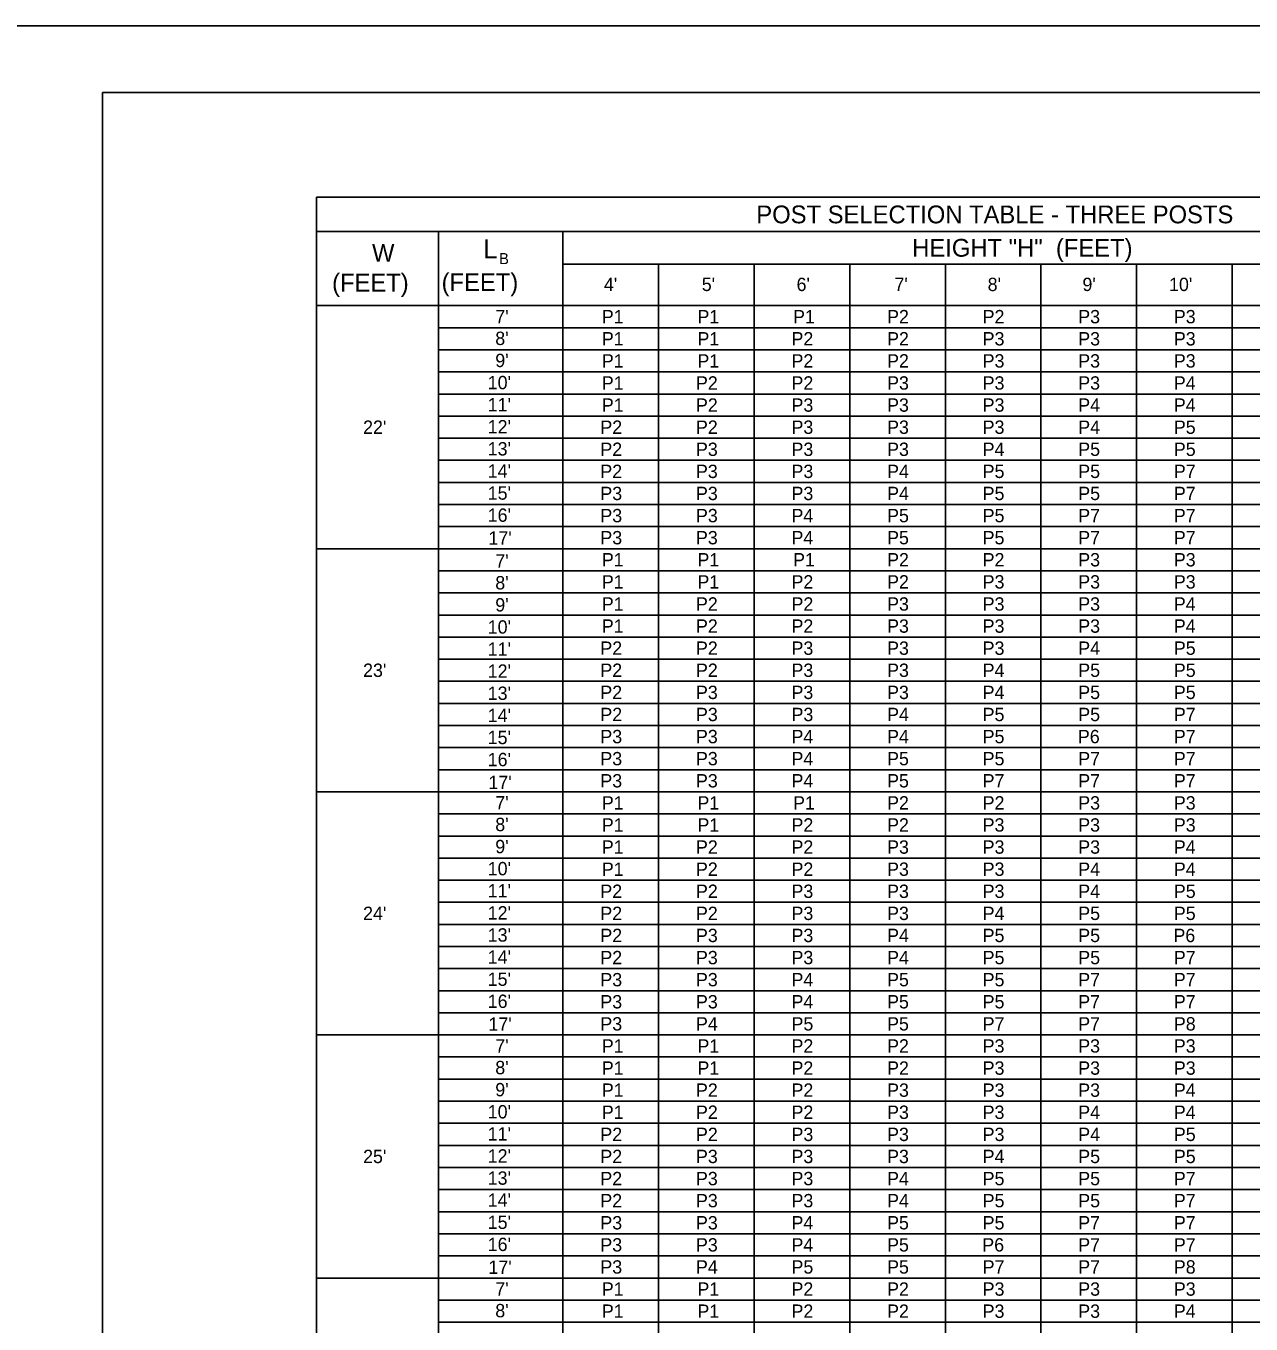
# Model space of a CAD drawing. Extents: x 637580 to 641008, y 294594 to 295782.
# Drawn here: x 640126.1 to 640401.8, y 295489.6 to 295781.6 of the extents above; entities that cross this region are included whole.
import ezdxf

# ---------------------------------------------------------------- set-up
doc = ezdxf.new("R2010")
doc.units = 0
for name, color, linetype in [('1', 7, 'Continuous'), ('2', 7, 'Continuous'), ('PLT-BNDY', 7, 'Continuous')]:
    doc.layers.add(name, color=color, linetype=linetype)

msp = doc.modelspace()

# ---------------------------------------------------------------- linework, layer by layer
at = {"layer": '1'}
for p, q in [((640143.31, 295766.63), (640929.31, 295766.63)), ((640143.31, 295766.63), (640143.31, 295202.63)), ((640191.43, 295226.43), (640191.43, 295743.08)), ((640191.43, 295743.08), (640526.66, 295743.08)), ((640191.43, 295735.41), (640526.66, 295735.41)), ((640218.95, 295226.43), (640218.95, 295735.41)), ((640191.43, 295718.7), (640526.66, 295718.7)), ((640191.43, 295664.01), (640526.66, 295664.01)), ((640191.43, 295609.31), (640526.66, 295609.31)), ((640191.43, 295554.61), (640526.66, 295554.61)), ((640191.43, 295499.91), (640526.66, 295499.91))]:
    msp.add_line(p, q, dxfattribs=at)
at = {"layer": '2'}
for p, q in [((640246.95, 295226.43), (640246.95, 295735.41)), ((640246.95, 295728.06), (640526.66, 295728.06)), ((640268.47, 295226.43), (640268.47, 295728.06)), ((640289.99, 295226.43), (640289.99, 295728.06)), ((640311.5, 295226.43), (640311.5, 295728.06)), ((640333.02, 295226.43), (640333.02, 295728.06)), ((640354.53, 295226.43), (640354.53, 295728.06)), ((640376.05, 295226.43), (640376.05, 295728.06)), ((640397.56, 295226.43), (640397.56, 295728.06)), ((640211.96, 295718.7), (640526.66, 295718.7)), ((640218.95, 295713.73), (640526.66, 295713.73)), ((640218.95, 295708.76), (640526.66, 295708.76)), ((640218.95, 295703.79), (640526.66, 295703.79)), ((640218.95, 295698.81), (640526.66, 295698.81)), ((640218.95, 295693.84), (640526.66, 295693.84)), ((640218.95, 295688.87), (640526.66, 295688.87)), ((640218.95, 295683.9), (640526.66, 295683.9)), ((640218.95, 295678.92), (640526.66, 295678.92)), ((640218.95, 295673.95), (640526.66, 295673.95)), ((640218.95, 295668.98), (640526.66, 295668.98)), ((640218.95, 295659.03), (640526.66, 295659.03)), ((640218.95, 295654.06), (640526.66, 295654.06)), ((640218.95, 295649.09), (640526.66, 295649.09)), ((640218.95, 295644.12), (640526.66, 295644.12)), ((640218.95, 295639.14), (640526.66, 295639.14)), ((640218.95, 295634.17), (640526.66, 295634.17)), ((640218.95, 295629.2), (640526.66, 295629.2)), ((640218.95, 295624.23), (640526.66, 295624.23)), ((640218.95, 295619.25), (640526.66, 295619.25)), ((640218.95, 295614.28), (640526.66, 295614.28)), ((640218.95, 295604.34), (640526.66, 295604.34)), ((640218.95, 295599.36), (640526.66, 295599.36)), ((640218.95, 295594.39), (640526.66, 295594.39)), ((640218.95, 295589.42), (640526.66, 295589.42)), ((640218.95, 295584.45), (640526.66, 295584.45)), ((640218.95, 295579.47), (640526.66, 295579.47)), ((640218.95, 295574.5), (640526.66, 295574.5)), ((640218.95, 295569.53), (640526.66, 295569.53)), ((640218.95, 295564.56), (640526.66, 295564.56)), ((640218.95, 295559.58), (640526.66, 295559.58)), ((640218.95, 295549.64), (640526.66, 295549.64)), ((640218.95, 295544.67), (640526.66, 295544.67)), ((640218.95, 295539.69), (640526.66, 295539.69)), ((640218.95, 295534.72), (640526.66, 295534.72)), ((640218.95, 295529.75), (640526.66, 295529.75)), ((640218.95, 295524.78), (640526.66, 295524.78)), ((640218.95, 295519.8), (640526.66, 295519.8)), ((640218.95, 295514.83), (640526.66, 295514.83)), ((640218.95, 295509.86), (640526.66, 295509.86)), ((640218.95, 295504.89), (640526.66, 295504.89)), ((640218.95, 295494.94), (640526.66, 295494.94)), ((640218.95, 295489.97), (640526.66, 295489.97))]:
    msp.add_line(p, q, dxfattribs=at)
at = {"layer": 'PLT-BNDY'}
msp.add_lwpolyline([(640103.31, 295781.63), (640944.31, 295781.63), (640944.31, 295187.63), (640103.31, 295187.63)], close=True, dxfattribs=at)

# ---------------------------------------------------------------- texts
at = {"layer": '1'}
for s, height, p in [('POST SELECTION TABLE - THREE POSTS', 4.003, (640290.47, 295737.22)), ('W', 4, (640203.96, 295728.57)), ('L', 4.3, (640228.99, 295729.34)), ('HEIGHT "H"  (FEET)', 4.003, (640325.56, 295729.71)), ('B', 2.5, (640232.55, 295728.03)), ('(FEET)', 4.003, (640194.97, 295721.87)), (' (FEET)', 4.003, (640218.14, 295721.99)), ("4'", 3, (640256.16, 295721.98)), ("5'", 3, (640278.19, 295721.98)), ("6'", 3, (640299.53, 295721.98)), ("7'", 3, (640321.57, 295721.98)), ("8'", 3, (640342.55, 295721.98)), ("9'", 3, (640363.89, 295721.98)), ("10'", 3, (640383.38, 295721.98)), ("7'", 3, (640231.71, 295714.72)), ('P1', 3, (640255.7, 295714.72)), ('P1', 3, (640277.22, 295714.72)), ('P1', 3, (640298.74, 295714.72)), ('P2', 3, (640319.91, 295714.72)), ('P2', 3, (640341.42, 295714.72)), ('P3', 3, (640362.94, 295714.72)), ('P3', 3, (640384.46, 295714.72)), ("8'", 3, (640231.71, 295709.84)), ('P1', 3, (640255.7, 295709.74)), ('P1', 3, (640277.22, 295709.74)), ('P2', 3, (640298.39, 295709.74)), ('P2', 3, (640319.91, 295709.74)), ('P3', 3, (640341.42, 295709.74)), ('P3', 3, (640362.94, 295709.74)), ('P3', 3, (640384.46, 295709.74)), ("9'", 3, (640231.71, 295704.87)), ('P1', 3, (640255.7, 295704.77)), ('P1', 3, (640277.22, 295704.77)), ('P2', 3, (640298.39, 295704.77)), ('P2', 3, (640319.91, 295704.77)), ('P3', 3, (640341.42, 295704.77)), ('P3', 3, (640362.94, 295704.77)), ('P3', 3, (640384.46, 295704.77)), ("10'", 3, (640230.01, 295699.89)), ('P1', 3, (640255.7, 295699.8)), ('P2', 3, (640276.88, 295699.8)), ('P2', 3, (640298.39, 295699.8)), ('P3', 3, (640319.91, 295699.8)), ('P3', 3, (640341.42, 295699.8)), ('P3', 3, (640362.94, 295699.8)), ('P4', 3, (640384.46, 295699.8)), ("11'", 3, (640230.01, 295694.92)), ('P1', 3, (640255.7, 295694.83)), ('P2', 3, (640276.88, 295694.83)), ('P3', 3, (640298.39, 295694.83)), ('P3', 3, (640319.91, 295694.83)), ('P3', 3, (640341.42, 295694.83)), ('P4', 3, (640362.94, 295694.83)), ('P4', 3, (640384.46, 295694.83)), ("22'", 3, (640201.95, 295689.85)), ("12'", 3, (640230.01, 295689.95)), ('P2', 3, (640255.36, 295689.85)), ('P2', 3, (640276.88, 295689.85)), ('P3', 3, (640298.39, 295689.85)), ('P3', 3, (640319.91, 295689.85)), ('P3', 3, (640341.42, 295689.85)), ('P4', 3, (640362.94, 295689.85)), ('P5', 3, (640384.46, 295689.85)), ("13'", 3, (640230.01, 295684.98)), ('P2', 3, (640255.36, 295684.88)), ('P3', 3, (640276.88, 295684.88)), ('P3', 3, (640298.39, 295684.88)), ('P3', 3, (640319.91, 295684.88)), ('P4', 3, (640341.42, 295684.88)), ('P5', 3, (640362.94, 295684.88)), ('P5', 3, (640384.46, 295684.88)), ("14'", 3, (640230.01, 295680)), ('P2', 3, (640255.36, 295679.91)), ('P3', 3, (640276.88, 295679.91)), ('P3', 3, (640298.39, 295679.91)), ('P4', 3, (640319.91, 295679.91)), ('P5', 3, (640341.42, 295679.91)), ('P5', 3, (640362.94, 295679.91)), ('P7', 3, (640384.46, 295679.91)), ("15'", 3, (640230.01, 295675.03)), ('P3', 3, (640255.36, 295674.94)), ('P3', 3, (640276.88, 295674.94)), ('P3', 3, (640298.39, 295674.94)), ('P4', 3, (640319.91, 295674.94)), ('P5', 3, (640341.42, 295674.94)), ('P5', 3, (640362.94, 295674.94)), ('P7', 3, (640384.46, 295674.94)), ("16'", 3, (640230.01, 295670.06)), ('P3', 3, (640255.36, 295669.96)), ('P3', 3, (640276.88, 295669.96)), ('P4', 3, (640298.39, 295669.96)), ('P5', 3, (640319.91, 295669.96)), ('P5', 3, (640341.42, 295669.96)), ('P7', 3, (640362.94, 295669.96)), ('P7', 3, (640384.46, 295669.96)), ("17'", 3, (640230.17, 295664.91)), ('P3', 3, (640255.36, 295664.99)), ('P3', 3, (640276.88, 295664.99)), ('P4', 3, (640298.39, 295664.99)), ('P5', 3, (640319.91, 295664.99)), ('P5', 3, (640341.42, 295664.99)), ('P7', 3, (640362.94, 295664.99)), ('P7', 3, (640384.46, 295664.99)), ("7'", 3, (640231.71, 295659.73)), ('P1', 3, (640255.7, 295660.02)), ('P1', 3, (640277.22, 295660.02)), ('P1', 3, (640298.74, 295660.02)), ('P2', 3, (640319.91, 295660.02)), ('P2', 3, (640341.42, 295660.02)), ('P3', 3, (640362.94, 295660.02)), ('P3', 3, (640384.46, 295660.02)), ("8'", 3, (640231.71, 295654.85)), ('P1', 3, (640255.7, 295655.05)), ('P1', 3, (640277.22, 295655.05)), ('P2', 3, (640298.39, 295655.05)), ('P2', 3, (640319.91, 295655.05)), ('P3', 3, (640341.42, 295655.05)), ('P3', 3, (640362.94, 295655.05)), ('P3', 3, (640384.46, 295655.05)), ("9'", 3, (640231.71, 295649.88)), ('P1', 3, (640255.7, 295650.07)), ('P2', 3, (640276.88, 295650.07)), ('P2', 3, (640298.39, 295650.07)), ('P3', 3, (640319.91, 295650.07)), ('P3', 3, (640341.42, 295650.07)), ('P3', 3, (640362.94, 295650.07)), ('P4', 3, (640384.46, 295650.07)), ("10'", 3, (640230.01, 295644.9)), ('P1', 3, (640255.7, 295645.1)), ('P2', 3, (640276.88, 295645.1)), ('P2', 3, (640298.39, 295645.1)), ('P3', 3, (640319.91, 295645.1)), ('P3', 3, (640341.42, 295645.1)), ('P3', 3, (640362.94, 295645.1)), ('P4', 3, (640384.46, 295645.1)), ("11'", 3, (640230.01, 295639.93)), ('P2', 3, (640255.36, 295640.13)), ('P2', 3, (640276.88, 295640.13)), ('P3', 3, (640298.39, 295640.13)), ('P3', 3, (640319.91, 295640.13)), ('P3', 3, (640341.42, 295640.13)), ('P4', 3, (640362.94, 295640.13)), ('P5', 3, (640384.46, 295640.13)), ("23'", 3, (640201.95, 295635.16)), ("12'", 3, (640230.01, 295634.96)), ('P2', 3, (640255.36, 295635.16)), ('P2', 3, (640276.88, 295635.16)), ('P3', 3, (640298.39, 295635.16)), ('P3', 3, (640319.91, 295635.16)), ('P4', 3, (640341.42, 295635.16)), ('P5', 3, (640362.94, 295635.16)), ('P5', 3, (640384.46, 295635.16)), ('P2', 3, (640255.36, 295630.18)), ('P3', 3, (640276.88, 295630.18)), ('P3', 3, (640298.39, 295630.18)), ('P3', 3, (640319.91, 295630.18)), ('P4', 3, (640341.42, 295630.18)), ('P5', 3, (640362.94, 295630.18)), ('P5', 3, (640384.46, 295630.18)), ("13'", 3, (640230.01, 295629.99)), ("14'", 3, (640230.01, 295625.01)), ('P2', 3, (640255.36, 295625.21)), ('P3', 3, (640276.88, 295625.21)), ('P3', 3, (640298.39, 295625.21)), ('P4', 3, (640319.91, 295625.21)), ('P5', 3, (640341.42, 295625.21)), ('P5', 3, (640362.94, 295625.21)), ('P7', 3, (640384.46, 295625.21)), ("15'", 3, (640230.01, 295620.04)), ('P3', 3, (640255.36, 295620.24)), ('P3', 3, (640276.88, 295620.24)), ('P4', 3, (640298.39, 295620.24)), ('P4', 3, (640319.91, 295620.24)), ('P5', 3, (640341.42, 295620.24)), ('P6', 3, (640362.86, 295620.24)), ('P7', 3, (640384.46, 295620.24)), ("16'", 3, (640230.01, 295615.07)), ('P3', 3, (640255.36, 295615.27)), ('P3', 3, (640276.88, 295615.27)), ('P4', 3, (640298.39, 295615.27)), ('P5', 3, (640319.91, 295615.27)), ('P5', 3, (640341.42, 295615.27)), ('P7', 3, (640362.94, 295615.27)), ('P7', 3, (640384.46, 295615.27)), ("17'", 3, (640230.17, 295609.92)), ('P3', 3, (640255.36, 295610.29)), ('P3', 3, (640276.88, 295610.29)), ('P4', 3, (640298.39, 295610.29)), ('P5', 3, (640319.91, 295610.29)), ('P7', 3, (640341.42, 295610.29)), ('P7', 3, (640362.94, 295610.29)), ('P7', 3, (640384.46, 295610.29)), ("7'", 3, (640231.71, 295605.34)), ('P1', 3, (640255.7, 295605.32)), ('P1', 3, (640277.22, 295605.32)), ('P1', 3, (640298.74, 295605.32)), ('P2', 3, (640319.91, 295605.32)), ('P2', 3, (640341.42, 295605.32)), ('P3', 3, (640362.94, 295605.32)), ('P3', 3, (640384.46, 295605.32)), ("8'", 3, (640231.71, 295600.46)), ('P1', 3, (640255.7, 295600.35)), ('P1', 3, (640277.22, 295600.35)), ('P2', 3, (640298.39, 295600.35)), ('P2', 3, (640319.91, 295600.35)), ('P3', 3, (640341.42, 295600.35)), ('P3', 3, (640362.94, 295600.35)), ('P3', 3, (640384.46, 295600.35)), ("9'", 3, (640231.71, 295595.49)), ('P1', 3, (640255.7, 295595.38)), ('P2', 3, (640276.88, 295595.38)), ('P2', 3, (640298.39, 295595.38)), ('P3', 3, (640319.91, 295595.38)), ('P3', 3, (640341.42, 295595.38)), ('P3', 3, (640362.94, 295595.38)), ('P4', 3, (640384.46, 295595.38)), ("10'", 3, (640230.01, 295590.52)), ('P1', 3, (640255.7, 295590.4)), ('P2', 3, (640276.88, 295590.4)), ('P2', 3, (640298.39, 295590.4)), ('P3', 3, (640319.91, 295590.4)), ('P3', 3, (640341.42, 295590.4)), ('P4', 3, (640362.94, 295590.4)), ('P4', 3, (640384.46, 295590.4)), ("11'", 3, (640230.01, 295585.54)), ('P2', 3, (640255.36, 295585.43)), ('P2', 3, (640276.88, 295585.43)), ('P3', 3, (640298.39, 295585.43)), ('P3', 3, (640319.91, 295585.43)), ('P3', 3, (640341.42, 295585.43)), ('P4', 3, (640362.94, 295585.43)), ('P5', 3, (640384.46, 295585.43)), ("24'", 3, (640201.95, 295580.46)), ("12'", 3, (640230.01, 295580.57)), ('P2', 3, (640255.36, 295580.46)), ('P2', 3, (640276.88, 295580.46)), ('P3', 3, (640298.39, 295580.46)), ('P3', 3, (640319.91, 295580.46)), ('P4', 3, (640341.42, 295580.46)), ('P5', 3, (640362.94, 295580.46)), ('P5', 3, (640384.46, 295580.46)), ("13'", 3, (640230.01, 295575.6)), ('P2', 3, (640255.36, 295575.49)), ('P3', 3, (640276.88, 295575.49)), ('P3', 3, (640298.39, 295575.49)), ('P4', 3, (640319.91, 295575.49)), ('P5', 3, (640341.42, 295575.49)), ('P5', 3, (640362.94, 295575.49)), ('P6', 3, (640384.37, 295575.49)), ("14'", 3, (640230.01, 295570.63)), ('P2', 3, (640255.36, 295570.51)), ('P3', 3, (640276.88, 295570.51)), ('P3', 3, (640298.39, 295570.51)), ('P4', 3, (640319.91, 295570.51)), ('P5', 3, (640341.42, 295570.51)), ('P5', 3, (640362.94, 295570.51)), ('P7', 3, (640384.46, 295570.51)), ("15'", 3, (640230.01, 295565.65)), ('P3', 3, (640255.36, 295565.54)), ('P3', 3, (640276.88, 295565.54)), ('P4', 3, (640298.39, 295565.54)), ('P5', 3, (640319.91, 295565.54)), ('P5', 3, (640341.42, 295565.54)), ('P7', 3, (640362.94, 295565.54)), ('P7', 3, (640384.46, 295565.54)), ("16'", 3, (640230.01, 295560.68)), ('P3', 3, (640255.36, 295560.57)), ('P3', 3, (640276.88, 295560.57)), ('P4', 3, (640298.39, 295560.57)), ('P5', 3, (640319.91, 295560.57)), ('P5', 3, (640341.42, 295560.57)), ('P7', 3, (640362.94, 295560.57)), ('P7', 3, (640384.46, 295560.57)), ("17'", 3, (640230.17, 295555.53)), ('P3', 3, (640255.36, 295555.6)), ('P4', 3, (640276.88, 295555.6)), ('P5', 3, (640298.39, 295555.6)), ('P5', 3, (640319.91, 295555.6)), ('P7', 3, (640341.42, 295555.6)), ('P7', 3, (640362.94, 295555.6)), ('P8', 3, (640384.46, 295555.6)), ("7'", 3, (640231.71, 295550.64)), ('P1', 3, (640255.7, 295550.62)), ('P1', 3, (640277.22, 295550.62)), ('P2', 3, (640298.39, 295550.62)), ('P2', 3, (640319.91, 295550.62)), ('P3', 3, (640341.42, 295550.62)), ('P3', 3, (640362.94, 295550.62)), ('P3', 3, (640384.46, 295550.62)), ("8'", 3, (640231.71, 295545.76)), ('P1', 3, (640255.7, 295545.65)), ('P1', 3, (640277.22, 295545.65)), ('P2', 3, (640298.39, 295545.65)), ('P2', 3, (640319.91, 295545.65)), ('P3', 3, (640341.42, 295545.65)), ('P3', 3, (640362.94, 295545.65)), ('P3', 3, (640384.46, 295545.65)), ("9'", 3, (640231.71, 295540.79)), ('P1', 3, (640255.7, 295540.68)), ('P2', 3, (640276.88, 295540.68)), ('P2', 3, (640298.39, 295540.68)), ('P3', 3, (640319.91, 295540.68)), ('P3', 3, (640341.42, 295540.68)), ('P3', 3, (640362.94, 295540.68)), ('P4', 3, (640384.46, 295540.68)), ("10'", 3, (640230.01, 295535.82)), ('P1', 3, (640255.7, 295535.71)), ('P2', 3, (640276.88, 295535.71)), ('P2', 3, (640298.39, 295535.71)), ('P3', 3, (640319.91, 295535.71)), ('P3', 3, (640341.42, 295535.71)), ('P4', 3, (640362.94, 295535.71)), ('P4', 3, (640384.46, 295535.71)), ("11'", 3, (640230.01, 295530.85)), ('P2', 3, (640255.36, 295530.73)), ('P2', 3, (640276.88, 295530.73)), ('P3', 3, (640298.39, 295530.73)), ('P3', 3, (640319.91, 295530.73)), ('P3', 3, (640341.42, 295530.73)), ('P4', 3, (640362.94, 295530.73)), ('P5', 3, (640384.46, 295530.73)), ("25'", 3, (640201.95, 295525.76)), ("12'", 3, (640230.01, 295525.87)), ('P2', 3, (640255.36, 295525.76)), ('P3', 3, (640276.88, 295525.76)), ('P3', 3, (640298.39, 295525.76)), ('P3', 3, (640319.91, 295525.76)), ('P4', 3, (640341.42, 295525.76)), ('P5', 3, (640362.94, 295525.76)), ('P5', 3, (640384.46, 295525.76)), ("13'", 3, (640230.01, 295520.9)), ('P2', 3, (640255.36, 295520.79)), ('P3', 3, (640276.88, 295520.79)), ('P3', 3, (640298.39, 295520.79)), ('P4', 3, (640319.91, 295520.79)), ('P5', 3, (640341.42, 295520.79)), ('P5', 3, (640362.94, 295520.79)), ('P7', 3, (640384.46, 295520.79)), ("14'", 3, (640230.01, 295515.93)), ('P2', 3, (640255.36, 295515.82)), ('P3', 3, (640276.88, 295515.82)), ('P3', 3, (640298.39, 295515.82)), ('P4', 3, (640319.91, 295515.82)), ('P5', 3, (640341.42, 295515.82)), ('P5', 3, (640362.94, 295515.82)), ('P7', 3, (640384.46, 295515.82)), ("15'", 3, (640230.01, 295510.96)), ('P3', 3, (640255.36, 295510.84)), ('P3', 3, (640276.88, 295510.84)), ('P4', 3, (640298.39, 295510.84)), ('P5', 3, (640319.91, 295510.84)), ('P5', 3, (640341.42, 295510.84)), ('P7', 3, (640362.94, 295510.84)), ('P7', 3, (640384.46, 295510.84)), ("16'", 3, (640230.01, 295505.98)), ('P3', 3, (640255.36, 295505.87)), ('P3', 3, (640276.88, 295505.87)), ('P4', 3, (640298.39, 295505.87)), ('P5', 3, (640319.91, 295505.87)), ('P6', 3, (640341.34, 295505.87)), ('P7', 3, (640362.94, 295505.87)), ('P7', 3, (640384.46, 295505.87)), ("17'", 3, (640230.17, 295500.84)), ('P3', 3, (640255.36, 295500.9)), ('P4', 3, (640276.88, 295500.9)), ('P5', 3, (640298.39, 295500.9)), ('P5', 3, (640319.91, 295500.9)), ('P7', 3, (640341.42, 295500.9)), ('P7', 3, (640362.94, 295500.9)), ('P8', 3, (640384.46, 295500.9)), ("7'", 3, (640231.71, 295495.95)), ('P1', 3, (640255.7, 295495.93)), ('P1', 3, (640277.22, 295495.93)), ('P2', 3, (640298.39, 295495.93)), ('P2', 3, (640319.91, 295495.93)), ('P3', 3, (640341.42, 295495.93)), ('P3', 3, (640362.94, 295495.93)), ('P3', 3, (640384.46, 295495.93)), ("8'", 3, (640231.71, 295491.07)), ('P1', 3, (640255.7, 295490.95)), ('P1', 3, (640277.22, 295490.95)), ('P2', 3, (640298.39, 295490.95)), ('P2', 3, (640319.91, 295490.95)), ('P3', 3, (640341.42, 295490.95)), ('P3', 3, (640362.94, 295490.95)), ('P4', 3, (640384.46, 295490.95))]:
    msp.add_text(s, height=height, dxfattribs=at).set_placement(p)

doc.saveas('drawing.dxf')
